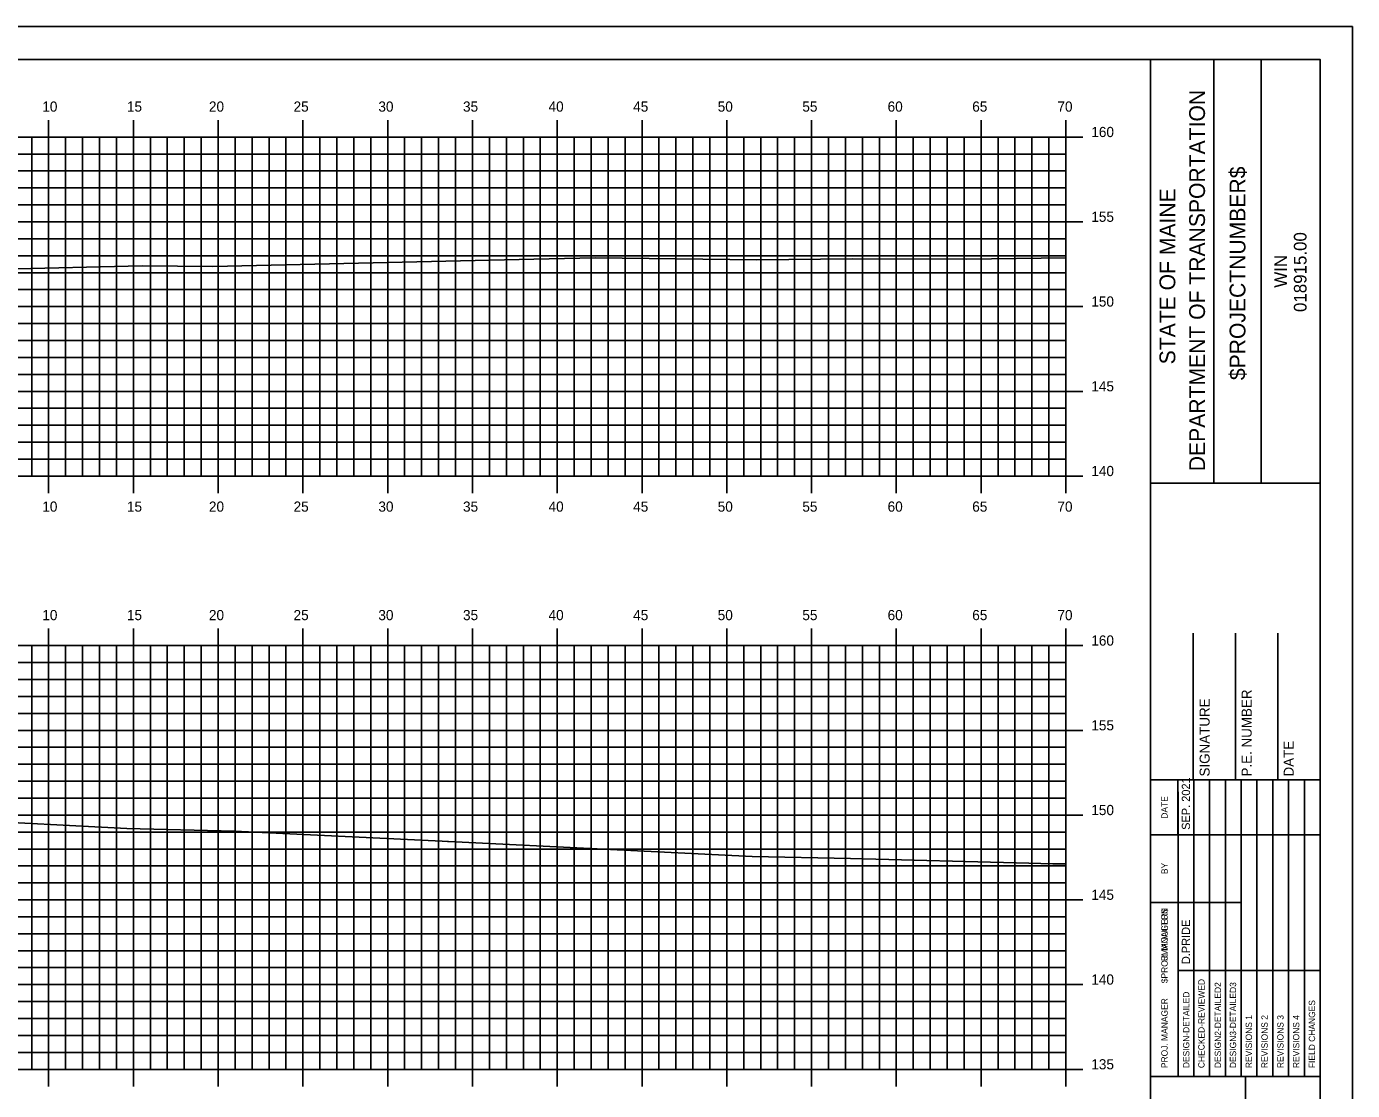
# Model space of a CAD drawing. Extents: x 852082 to 852254, y 365876 to 365986.
# Drawn here: x 852173.9 to 852252.1, y 365923 to 365985.8 of the extents above; entities that cross this region are included whole.
import ezdxf

# ---------------------------------------------------------------- set-up
doc = ezdxf.new("R2010")
doc.units = 0
for name, color, linetype in [('BORDER', 7, 'Continuous'), ('H_V ANNOTATION', 7, 'Continuous'), ('MAJOR', 7, 'Continuous'), ('MINOR', 7, 'Continuous'), ('PLOT BOUNDARY', 7, 'Continuous'), ('S_Roadway_Centerline', 7, 'Continuous')]:
    doc.layers.add(name, color=color, linetype=linetype)

msp = doc.modelspace()

# ---------------------------------------------------------------- linework, layer by layer
at = {"layer": 'BORDER'}
for p, q in [((852240.168, 365878.833), (852240.168, 365983.833)), ((852243.897, 365958.83), (852243.897, 365983.83)), ((852246.692, 365958.83), (852246.692, 365983.83)), ((852240.169, 365958.827), (852250.168, 365958.827)), ((852242.668, 365941.336), (852242.668, 365949.984)), ((852245.168, 365941.336), (852245.168, 365949.984)), ((852247.668, 365941.336), (852247.668, 365949.984)), ((852240.168, 365941.336), (852250.168, 365941.336)), ((852240.168, 365923.836), (852250.168, 365923.836)), ((852245.759, 365888.836), (852245.759, 365923.836))]:
    msp.add_line(p, q, dxfattribs=at)
msp.add_lwpolyline([(852090.168, 365878.833), (852250.168, 365878.833), (852250.168, 365983.833), (852090.168, 365983.833)], close=True, dxfattribs=at)
for points in [[(852241.783, 365938.086), (852241.783, 365941.336)], [(852241.784, 365923.839), (852241.784, 365940.63)], [(852242.716, 365923.839), (852242.716, 365941.336)], [(852243.647, 365941.336), (852243.647, 365923.839)], [(852244.579, 365923.839), (852244.579, 365941.336)], [(852245.511, 365923.839), (852245.511, 365941.336)], [(852246.442, 365923.839), (852246.442, 365941.336)], [(852247.374, 365923.839), (852247.374, 365941.336)], [(852248.306, 365923.839), (852248.306, 365941.336)], [(852249.237, 365923.839), (852249.237, 365941.336)], [(852240.168, 365938.086), (852250.168, 365938.086)], [(852240.168, 365934.086), (852241.784, 365934.086)], [(852241.783, 365934.086), (852245.51, 365934.086)], [(852241.783, 365930.086), (852250.168, 365930.086)]]:
    msp.add_lwpolyline(points, dxfattribs=at)
at = {"layer": 'MAJOR'}
for p, q in [((852175.168, 365980.253), (852175.168, 365979.251)), ((852180.168, 365980.253), (852180.168, 365979.251)), ((852185.168, 365980.253), (852185.168, 365979.251)), ((852190.168, 365980.253), (852190.168, 365979.251)), ((852195.168, 365980.253), (852195.168, 365979.251)), ((852200.168, 365980.253), (852200.168, 365979.251)), ((852205.168, 365980.253), (852205.168, 365979.251)), ((852210.168, 365980.253), (852210.168, 365979.251)), ((852215.168, 365980.253), (852215.168, 365979.251)), ((852220.168, 365980.253), (852220.168, 365979.251)), ((852225.168, 365980.253), (852225.168, 365979.251)), ((852230.168, 365980.253), (852230.168, 365979.251)), ((852235.168, 365980.253), (852235.168, 365979.251)), ((852095.168, 365979.251), (852235.168, 365979.251)), ((852095.168, 365979.251), (852235.168, 365979.251)), ((852175.168, 365959.251), (852175.168, 365979.251)), ((852180.168, 365959.251), (852180.168, 365979.251)), ((852185.168, 365959.251), (852185.168, 365979.251)), ((852190.168, 365959.251), (852190.168, 365979.251)), ((852195.168, 365959.251), (852195.168, 365979.251)), ((852200.168, 365959.251), (852200.168, 365979.251)), ((852205.168, 365959.251), (852205.168, 365979.251)), ((852210.168, 365959.251), (852210.168, 365979.251)), ((852215.168, 365959.251), (852215.168, 365979.251)), ((852220.168, 365959.251), (852220.168, 365979.251)), ((852225.168, 365959.251), (852225.168, 365979.251)), ((852230.168, 365959.251), (852230.168, 365979.251)), ((852236.17, 365979.251), (852234.166, 365979.251)), ((852235.168, 365959.251), (852235.168, 365979.251)), ((852235.168, 365959.251), (852235.168, 365979.251)), ((852095.168, 365974.251), (852235.168, 365974.251)), ((852236.17, 365974.251), (852234.166, 365974.251)), ((852095.168, 365969.251), (852235.168, 365969.251)), ((852236.17, 365969.251), (852234.166, 365969.251)), ((852095.168, 365964.251), (852235.168, 365964.251)), ((852236.17, 365964.251), (852234.166, 365964.251)), ((852095.168, 365959.251), (852235.168, 365959.251)), ((852095.168, 365959.251), (852235.168, 365959.251)), ((852175.168, 365958.249), (852175.168, 365959.251)), ((852180.168, 365958.249), (852180.168, 365959.251)), ((852185.168, 365958.249), (852185.168, 365959.251)), ((852190.168, 365958.249), (852190.168, 365959.251)), ((852195.168, 365958.249), (852195.168, 365959.251)), ((852200.168, 365958.249), (852200.168, 365959.251)), ((852205.168, 365958.249), (852205.168, 365959.251)), ((852210.168, 365958.249), (852210.168, 365959.251)), ((852215.168, 365958.249), (852215.168, 365959.251)), ((852220.168, 365958.249), (852220.168, 365959.251)), ((852225.168, 365958.249), (852225.168, 365959.251)), ((852230.168, 365958.249), (852230.168, 365959.251)), ((852236.17, 365959.251), (852234.166, 365959.251)), ((852235.168, 365958.249), (852235.168, 365959.251)), ((852175.168, 365950.253), (852175.168, 365949.251)), ((852180.168, 365950.253), (852180.168, 365949.251)), ((852185.168, 365950.253), (852185.168, 365949.251)), ((852190.168, 365950.253), (852190.168, 365949.251)), ((852195.168, 365950.253), (852195.168, 365949.251)), ((852200.168, 365950.253), (852200.168, 365949.251)), ((852205.168, 365950.253), (852205.168, 365949.251)), ((852210.168, 365950.253), (852210.168, 365949.251)), ((852215.168, 365950.253), (852215.168, 365949.251)), ((852220.168, 365950.253), (852220.168, 365949.251)), ((852225.168, 365950.253), (852225.168, 365949.251)), ((852230.168, 365950.253), (852230.168, 365949.251)), ((852235.168, 365950.253), (852235.168, 365949.251)), ((852095.168, 365949.251), (852235.168, 365949.251)), ((852095.168, 365949.251), (852235.168, 365949.251)), ((852175.168, 365924.251), (852175.168, 365949.251)), ((852180.168, 365924.251), (852180.168, 365949.251)), ((852185.168, 365924.251), (852185.168, 365949.251)), ((852190.168, 365924.251), (852190.168, 365949.251)), ((852195.168, 365924.251), (852195.168, 365949.251)), ((852200.168, 365924.251), (852200.168, 365949.251)), ((852205.168, 365924.251), (852205.168, 365949.251)), ((852210.168, 365924.251), (852210.168, 365949.251)), ((852215.168, 365924.251), (852215.168, 365949.251)), ((852220.168, 365924.251), (852220.168, 365949.251)), ((852225.168, 365924.251), (852225.168, 365949.251)), ((852230.168, 365924.251), (852230.168, 365949.251)), ((852236.17, 365949.251), (852234.166, 365949.251)), ((852235.168, 365924.251), (852235.168, 365949.251)), ((852235.168, 365924.251), (852235.168, 365949.251)), ((852095.168, 365944.251), (852235.168, 365944.251)), ((852236.17, 365944.251), (852234.166, 365944.251)), ((852095.168, 365939.251), (852235.168, 365939.251)), ((852236.17, 365939.251), (852234.166, 365939.251)), ((852095.168, 365934.251), (852235.168, 365934.251)), ((852236.17, 365934.251), (852234.166, 365934.251)), ((852095.168, 365929.251), (852235.168, 365929.251)), ((852236.17, 365929.251), (852234.166, 365929.251)), ((852095.168, 365924.251), (852235.168, 365924.251)), ((852095.168, 365924.251), (852235.168, 365924.251)), ((852175.168, 365923.249), (852175.168, 365924.251)), ((852180.168, 365923.249), (852180.168, 365924.251)), ((852185.168, 365923.249), (852185.168, 365924.251)), ((852190.168, 365923.249), (852190.168, 365924.251)), ((852195.168, 365923.249), (852195.168, 365924.251)), ((852200.168, 365923.249), (852200.168, 365924.251)), ((852205.168, 365923.249), (852205.168, 365924.251)), ((852210.168, 365923.249), (852210.168, 365924.251)), ((852215.168, 365923.249), (852215.168, 365924.251)), ((852220.168, 365923.249), (852220.168, 365924.251)), ((852225.168, 365923.249), (852225.168, 365924.251)), ((852230.168, 365923.249), (852230.168, 365924.251)), ((852236.17, 365924.251), (852234.166, 365924.251)), ((852235.168, 365923.249), (852235.168, 365924.251))]:
    msp.add_line(p, q, dxfattribs=at)
at = {"layer": 'MINOR'}
for p, q in [((852174.168, 365959.251), (852174.168, 365979.251)), ((852176.168, 365959.251), (852176.168, 365979.251)), ((852177.168, 365959.251), (852177.168, 365979.251)), ((852178.168, 365959.251), (852178.168, 365979.251)), ((852179.168, 365959.251), (852179.168, 365979.251)), ((852181.168, 365959.251), (852181.168, 365979.251)), ((852182.168, 365959.251), (852182.168, 365979.251)), ((852183.168, 365959.251), (852183.168, 365979.251)), ((852184.168, 365959.251), (852184.168, 365979.251)), ((852186.168, 365959.251), (852186.168, 365979.251)), ((852187.168, 365959.251), (852187.168, 365979.251)), ((852188.168, 365959.251), (852188.168, 365979.251)), ((852189.168, 365959.251), (852189.168, 365979.251)), ((852191.168, 365959.251), (852191.168, 365979.251)), ((852192.168, 365959.251), (852192.168, 365979.251)), ((852193.168, 365959.251), (852193.168, 365979.251)), ((852194.168, 365959.251), (852194.168, 365979.251)), ((852196.168, 365959.251), (852196.168, 365979.251)), ((852197.168, 365959.251), (852197.168, 365979.251)), ((852198.168, 365959.251), (852198.168, 365979.251)), ((852199.168, 365959.251), (852199.168, 365979.251)), ((852201.168, 365959.251), (852201.168, 365979.251)), ((852202.168, 365959.251), (852202.168, 365979.251)), ((852203.168, 365959.251), (852203.168, 365979.251)), ((852204.168, 365959.251), (852204.168, 365979.251)), ((852206.168, 365959.251), (852206.168, 365979.251)), ((852207.168, 365959.251), (852207.168, 365979.251)), ((852208.168, 365959.251), (852208.168, 365979.251)), ((852209.168, 365959.251), (852209.168, 365979.251)), ((852211.168, 365959.251), (852211.168, 365979.251)), ((852212.168, 365959.251), (852212.168, 365979.251)), ((852213.168, 365959.251), (852213.168, 365979.251)), ((852214.168, 365959.251), (852214.168, 365979.251)), ((852216.168, 365959.251), (852216.168, 365979.251)), ((852217.168, 365959.251), (852217.168, 365979.251)), ((852218.168, 365959.251), (852218.168, 365979.251)), ((852219.168, 365959.251), (852219.168, 365979.251)), ((852221.168, 365959.251), (852221.168, 365979.251)), ((852222.168, 365959.251), (852222.168, 365979.251)), ((852223.168, 365959.251), (852223.168, 365979.251)), ((852224.168, 365959.251), (852224.168, 365979.251)), ((852226.168, 365959.251), (852226.168, 365979.251)), ((852227.168, 365959.251), (852227.168, 365979.251)), ((852228.168, 365959.251), (852228.168, 365979.251)), ((852229.168, 365959.251), (852229.168, 365979.251)), ((852231.168, 365959.251), (852231.168, 365979.251)), ((852232.168, 365959.251), (852232.168, 365979.251)), ((852233.168, 365959.251), (852233.168, 365979.251)), ((852234.168, 365959.251), (852234.168, 365979.251)), ((852095.168, 365978.251), (852235.168, 365978.251)), ((852235.168, 365978.251), (852234.166, 365978.251)), ((852095.168, 365977.251), (852235.168, 365977.251)), ((852235.168, 365977.251), (852234.166, 365977.251)), ((852095.168, 365976.251), (852235.168, 365976.251)), ((852235.168, 365976.251), (852234.166, 365976.251)), ((852095.168, 365975.251), (852235.168, 365975.251)), ((852235.168, 365975.251), (852234.166, 365975.251)), ((852095.168, 365973.251), (852235.168, 365973.251)), ((852235.168, 365973.251), (852234.166, 365973.251)), ((852095.168, 365972.251), (852235.168, 365972.251)), ((852235.168, 365972.251), (852234.166, 365972.251)), ((852095.168, 365971.251), (852235.168, 365971.251)), ((852235.168, 365971.251), (852234.166, 365971.251)), ((852095.168, 365970.251), (852235.168, 365970.251)), ((852235.168, 365970.251), (852234.166, 365970.251)), ((852095.168, 365968.251), (852235.168, 365968.251)), ((852235.168, 365968.251), (852234.166, 365968.251)), ((852095.168, 365967.251), (852235.168, 365967.251)), ((852235.168, 365967.251), (852234.166, 365967.251)), ((852095.168, 365966.251), (852235.168, 365966.251)), ((852235.168, 365966.251), (852234.166, 365966.251)), ((852095.168, 365965.251), (852235.168, 365965.251)), ((852235.168, 365965.251), (852234.166, 365965.251)), ((852095.168, 365963.251), (852235.168, 365963.251)), ((852235.168, 365963.251), (852234.166, 365963.251)), ((852095.168, 365962.251), (852235.168, 365962.251)), ((852235.168, 365962.251), (852234.166, 365962.251)), ((852095.168, 365961.251), (852235.168, 365961.251)), ((852235.168, 365961.251), (852234.166, 365961.251)), ((852095.168, 365960.251), (852235.168, 365960.251)), ((852235.168, 365960.251), (852234.166, 365960.251)), ((852174.168, 365924.251), (852174.168, 365949.251)), ((852176.168, 365924.251), (852176.168, 365949.251)), ((852177.168, 365924.251), (852177.168, 365949.251)), ((852178.168, 365924.251), (852178.168, 365949.251)), ((852179.168, 365924.251), (852179.168, 365949.251)), ((852181.168, 365924.251), (852181.168, 365949.251)), ((852182.168, 365924.251), (852182.168, 365949.251)), ((852183.168, 365924.251), (852183.168, 365949.251)), ((852184.168, 365924.251), (852184.168, 365949.251)), ((852186.168, 365924.251), (852186.168, 365949.251)), ((852187.168, 365924.251), (852187.168, 365949.251)), ((852188.168, 365924.251), (852188.168, 365949.251)), ((852189.168, 365924.251), (852189.168, 365949.251)), ((852191.168, 365924.251), (852191.168, 365949.251)), ((852192.168, 365924.251), (852192.168, 365949.251)), ((852193.168, 365924.251), (852193.168, 365949.251)), ((852194.168, 365924.251), (852194.168, 365949.251)), ((852196.168, 365924.251), (852196.168, 365949.251)), ((852197.168, 365924.251), (852197.168, 365949.251)), ((852198.168, 365924.251), (852198.168, 365949.251)), ((852199.168, 365924.251), (852199.168, 365949.251)), ((852201.168, 365924.251), (852201.168, 365949.251)), ((852202.168, 365924.251), (852202.168, 365949.251)), ((852203.168, 365924.251), (852203.168, 365949.251)), ((852204.168, 365924.251), (852204.168, 365949.251)), ((852206.168, 365924.251), (852206.168, 365949.251)), ((852207.168, 365924.251), (852207.168, 365949.251)), ((852208.168, 365924.251), (852208.168, 365949.251)), ((852209.168, 365924.251), (852209.168, 365949.251)), ((852211.168, 365924.251), (852211.168, 365949.251)), ((852212.168, 365924.251), (852212.168, 365949.251)), ((852213.168, 365924.251), (852213.168, 365949.251)), ((852214.168, 365924.251), (852214.168, 365949.251)), ((852216.168, 365924.251), (852216.168, 365949.251)), ((852217.168, 365924.251), (852217.168, 365949.251)), ((852218.168, 365924.251), (852218.168, 365949.251)), ((852219.168, 365924.251), (852219.168, 365949.251)), ((852221.168, 365924.251), (852221.168, 365949.251)), ((852222.168, 365924.251), (852222.168, 365949.251)), ((852223.168, 365924.251), (852223.168, 365949.251)), ((852224.168, 365924.251), (852224.168, 365949.251)), ((852226.168, 365924.251), (852226.168, 365949.251)), ((852227.168, 365924.251), (852227.168, 365949.251)), ((852228.168, 365924.251), (852228.168, 365949.251)), ((852229.168, 365924.251), (852229.168, 365949.251)), ((852231.168, 365924.251), (852231.168, 365949.251)), ((852232.168, 365924.251), (852232.168, 365949.251)), ((852233.168, 365924.251), (852233.168, 365949.251)), ((852234.168, 365924.251), (852234.168, 365949.251)), ((852095.168, 365948.251), (852235.168, 365948.251)), ((852235.168, 365948.251), (852234.166, 365948.251)), ((852095.168, 365947.251), (852235.168, 365947.251)), ((852235.168, 365947.251), (852234.166, 365947.251)), ((852095.168, 365946.251), (852235.168, 365946.251)), ((852235.168, 365946.251), (852234.166, 365946.251)), ((852095.168, 365945.251), (852235.168, 365945.251)), ((852235.168, 365945.251), (852234.166, 365945.251)), ((852095.168, 365943.251), (852235.168, 365943.251)), ((852235.168, 365943.251), (852234.166, 365943.251)), ((852095.168, 365942.251), (852235.168, 365942.251)), ((852235.168, 365942.251), (852234.166, 365942.251)), ((852095.168, 365941.251), (852235.168, 365941.251)), ((852235.168, 365941.251), (852234.166, 365941.251)), ((852095.168, 365940.251), (852235.168, 365940.251)), ((852235.168, 365940.251), (852234.166, 365940.251)), ((852095.168, 365938.251), (852235.168, 365938.251)), ((852235.168, 365938.251), (852234.166, 365938.251)), ((852095.168, 365937.251), (852235.168, 365937.251)), ((852235.168, 365937.251), (852234.166, 365937.251)), ((852095.168, 365936.251), (852235.168, 365936.251)), ((852235.168, 365936.251), (852234.166, 365936.251)), ((852095.168, 365935.251), (852235.168, 365935.251)), ((852235.168, 365935.251), (852234.166, 365935.251)), ((852095.168, 365933.251), (852235.168, 365933.251)), ((852235.168, 365933.251), (852234.166, 365933.251)), ((852095.168, 365932.251), (852235.168, 365932.251)), ((852235.168, 365932.251), (852234.166, 365932.251)), ((852095.168, 365931.251), (852235.168, 365931.251)), ((852235.168, 365931.251), (852234.166, 365931.251)), ((852095.168, 365930.251), (852235.168, 365930.251)), ((852235.168, 365930.251), (852234.166, 365930.251)), ((852095.168, 365928.251), (852235.168, 365928.251)), ((852235.168, 365928.251), (852234.166, 365928.251)), ((852095.168, 365927.251), (852235.168, 365927.251)), ((852235.168, 365927.251), (852234.166, 365927.251)), ((852095.168, 365926.251), (852235.168, 365926.251)), ((852235.168, 365926.251), (852234.166, 365926.251)), ((852095.168, 365925.251), (852235.168, 365925.251)), ((852235.168, 365925.251), (852234.166, 365925.251))]:
    msp.add_line(p, q, dxfattribs=at)
at = {"layer": 'PLOT BOUNDARY'}
msp.add_lwpolyline([(852082.075, 365875.774), (852252.075, 365875.774), (852252.075, 365985.774), (852082.075, 365985.774)], close=True, dxfattribs=at)
at = {"layer": 'S_Roadway_Centerline'}
for points in [[(852172.495, 365971.458), (852180.691, 365971.651), (852184.858, 365971.621), (852199.471, 365971.947), (852203.792, 365972.049), (852207.412, 365972.131), (852216.935, 365972.01), (852222.589, 365972.069), (852229.326, 365972.058), (852235.168, 365972.127)], [(852169.996, 365938.978), (852179.789, 365938.46), (852186.133, 365938.297), (852198.379, 365937.72), (852198.69, 365937.691), (852198.745, 365937.686), (852199.176, 365937.67), (852216.665, 365936.801), (852222.474, 365936.692), (852232.989, 365936.413), (852234.397, 365936.385), (852235.168, 365936.369)]]:
    msp.add_lwpolyline(points, dxfattribs=at)

# ---------------------------------------------------------------- texts
at = {"layer": 'BORDER'}
for s, height, p in [('DEPARTMENT OF TRANSPORTATION', 0.93176, (852243.375, 365959.539)), ('$PROJECTNUMBER$', 0.93176, (852245.76, 365964.912)), ('STATE OF MAINE', 0.93176, (852241.624, 365965.845)), ('018915.00', 0.7453, (852249.364, 365968.931)), ('WIN', 0.7453, (852248.205, 365970.363)), ('SIGNATURE', 0.5906, (852243.649, 365941.528)), ('P.E. NUMBER', 0.59055, (852246.129, 365941.528)), ('DATE', 0.5906, (852248.609, 365941.528)), ('SEP. 2021', 0.4845, (852242.491, 365938.382)), ('DATE', 0.3714, (852241.173, 365939.042)), ('BY', 0.3714, (852241.173, 365935.771)), ('$PROJMANAGER$', 0.37275, (852241.173, 365929.331)), ('R. MOULTON', 0.3727, (852241.173, 365930.639)), ('D.PRIDE', 0.4845, (852242.491, 365930.459)), ('CHECKED-REVIEWED', 0.37275, (852243.349, 365924.324)), ('DESIGN2-DETAILED2', 0.37275, (852244.318, 365924.324)), ('DESIGN3-DETAILED3', 0.37275, (852245.213, 365924.324)), ('PROJ. MANAGER', 0.37275, (852241.173, 365924.324)), ('DESIGN-DETAILED', 0.37275, (852242.455, 365924.324)), ('FIELD CHANGES', 0.37275, (852249.871, 365924.324)), ('REVISIONS 1', 0.37275, (852246.144, 365924.324)), ('REVISIONS 2', 0.37275, (852247.076, 365924.324)), ('REVISIONS 3', 0.37275, (852248.008, 365924.324)), ('REVISIONS 4', 0.37275, (852248.939, 365924.324))]:
    msp.add_text(s, height=height, rotation=90, dxfattribs=at).set_placement(p)
at = {"layer": 'H_V ANNOTATION'}
for s, p in [('10', (852174.793, 365980.751)), ('15', (852179.785, 365980.751)), ('20', (852184.622, 365980.751)), ('25', (852189.614, 365980.751)), ('30', (852194.617, 365980.751)), ('35', (852199.609, 365980.751)), ('40', (852204.654, 365980.751)), ('45', (852209.646, 365980.751)), ('50', (852214.633, 365980.751)), ('55', (852219.625, 365980.751)), ('60', (852224.654, 365980.751)), ('65', (852229.646, 365980.751)), ('70', (852234.67, 365980.751)), ('160', (852236.668, 365979.251)), ('155', (852236.668, 365974.251)), ('150', (852236.668, 365969.251)), ('145', (852236.668, 365964.251)), ('140', (852236.668, 365959.251)), ('10', (852174.793, 365957.151)), ('15', (852179.785, 365957.151)), ('20', (852184.622, 365957.151)), ('25', (852189.614, 365957.151)), ('30', (852194.617, 365957.151)), ('35', (852199.609, 365957.151)), ('40', (852204.654, 365957.151)), ('45', (852209.646, 365957.151)), ('50', (852214.633, 365957.151)), ('55', (852219.625, 365957.151)), ('60', (852224.654, 365957.151)), ('65', (852229.646, 365957.151)), ('70', (852234.67, 365957.151)), ('10', (852174.793, 365950.751)), ('15', (852179.785, 365950.751)), ('20', (852184.622, 365950.751)), ('25', (852189.614, 365950.751)), ('30', (852194.617, 365950.751)), ('35', (852199.609, 365950.751)), ('40', (852204.654, 365950.751)), ('45', (852209.646, 365950.751)), ('50', (852214.633, 365950.751)), ('55', (852219.625, 365950.751)), ('60', (852224.654, 365950.751)), ('65', (852229.646, 365950.751)), ('70', (852234.67, 365950.751)), ('160', (852236.668, 365949.251)), ('155', (852236.668, 365944.251)), ('150', (852236.668, 365939.251)), ('145', (852236.668, 365934.251)), ('140', (852236.668, 365929.251)), ('135', (852236.668, 365924.251))]:
    msp.add_text(s, height=0.6, dxfattribs=at).set_placement(p)

doc.saveas('drawing.dxf')
